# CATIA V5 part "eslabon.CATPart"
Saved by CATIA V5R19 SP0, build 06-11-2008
Part number: eslabon
Material "Dull Blue": density 7860 kg/m3, Young's modulus 2e+11 Pa, Poisson ratio 0.266
Material "Dull Blue": density 7860 kg/m3, Young's modulus 2e+11 Pa, Poisson ratio 0.266
Bounding box of the stored display mesh (mm): x 189.734 to 215.134, y -369.65 to 369.65, z 11038.485 to 11955.485
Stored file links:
  E:\Luis\Dropbox\3DIT\Parking\planos\cat 3 dit park8\Cadena\eslabon.CATPart
  E:\Luis\Dropbox\3DIT\Parking\planos\cat 3 dit park8\Cadena\Eslabon de Cadena.........................................CATProduct
  E:\Luis\Dropbox\3DIT\Parking\planos\cat 3 dit park8\Cadena\ensamble unico eslabon.CATProduct
  E:\Luis\Dropbox\3DIT\Parking\planos\cat 3 dit park8\Cadena\Soportecuna.CATProduct
  E:\Luis\Dropbox\3DIT\Parking\planos\cat 3 dit park8\ensamble Parking3d.CATProduct
  C:\Program Files (x86)\Dassault Systemes\B19\intel_a\startup\materials\Catalog.CATMaterial
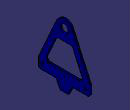
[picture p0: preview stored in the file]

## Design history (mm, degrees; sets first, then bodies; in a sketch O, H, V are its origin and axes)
External parameters (linked from other documents)
  External.P = 625
  External.b1 = 63.5
  External.b2 = 50.8
  External.d2 = 38.1
  External.g = 50.8
  External.LE = 600
Body1 (main body), material "Dull Blue"
  DatumSurface1
  DatumCurve1
  Sketch1, origin (410.9081, 7.5, 9247.3264), H (0, 1, 0), V (0, 0, 1), geometry linked from another document
  Sketch2, origin (410.9081, -1812.5, 6922.3264), H (0, 1, 0), V (0, 0, 1), geometry linked from another document
  Sketch3, origin (313.2342, -1812.5, 4597.3264), H (0, 1, 0), V (0, 0, 1), geometry linked from another document
  Sketch4 on DatumSurface4, origin (202.4342, 0, 0), H (0, 1, 0), V (0, 0, 1)
    point P2 (-312.5, 11235.4854)
    construction line L1 (0, 11835.4854) -> (0, 11235.4854)
    point P3 (0, 11235.4854)
    construction line L2 (0, 11835.4854) -> (-312.5, 11235.4854)
    line L3 (-109.3401, 11884.9296) -> (-369.65, 11309.2854)
    point P4 (-369.65, 11309.2854)
    circle A1 centre (0, 11835.4854) radius 60
    point P5 (0, 11869.2854)
    circle A2 centre (-312.5, 11235.4854) radius 19.05
    point P6 (-303.7001, 11252.3811)
    point P7 (487.5, 10734.2854)
    line L4 (-369.65, 11309.2854) -> (-369.65, 11176.963)
    point P8 (-369.65, 11072.4854)
    point P9 (-369.65, 11159.2854)
    circle A3 centre (0, 11235.4854) radius 9.525
    line L5 (-114.1377, 11159.2854) -> (-351.9723, 11159.2854)
    point P10 (-114.1377, 11159.2854)
    line L6 (-114.1377, 11159.2854) -> (-60, 11038.4854)
    point P11 (-60, 11038.4854)
    line L7 (-60, 11038.4854) -> (0, 11038.4854)
    point P12 (0, 11038.4854)
    line L8 (-369.65, 11176.963) -> (-351.9723, 11159.2854)
    point P13 (-369.65, 11176.963)
    point P14 (-351.9723, 11159.2854)
    construction line L9 (0, 11551.55) -> (0, 11955.4854)
    point P15 (0, 11551.55)
    arc A4 centre (0, 11835.4854) radius 120 from (0, 11955.4854) to (-109.3401, 11884.9296) ccw
    point P16 (0, 11835.4854)
    point P17 (0, 11955.4854)
    point P18 (0, 11955.4854)
    point P19 (-109.3401, 11884.9296)
    point P20 (109.3401, 11884.9296)
    point P21 (0, 11955.4854)
    arc A5 centre (0, 11835.4854) radius 120 from (0, 11955.4854) to (109.3401, 11884.9296) cw
    point P23 (369.65, 11309.2854)
    line L10 (109.3401, 11884.9296) -> (369.65, 11309.2854)
    point P24 (369.65, 11176.963)
    line L11 (369.65, 11309.2854) -> (369.65, 11176.963)
    point P25 (351.9723, 11159.2854)
    point P26 (114.1377, 11159.2854)
    line L12 (114.1377, 11159.2854) -> (351.9723, 11159.2854)
    point P27 (60, 11038.4854)
    line L13 (114.1377, 11159.2854) -> (60, 11038.4854)
    point P28 (0, 11038.4854)
    line L14 (60, 11038.4854) -> (0, 11038.4854)
    circle A6 centre (312.5, 11235.4854) radius 19.05
    line L15 (369.65, 11176.963) -> (351.9723, 11159.2854)
    radius A1 = 60
    radius A2 = 19.05 {= External.d2 /1000/2}
    length L1 = 600 {= External.LE /1000}
    distance P2 L4 = 57.15 {= External.d2 *1.5/1000}
    length L7 = 60
    distance P4 P9 = 150
    distance P10 P9 = 255.5123 (reference)
    angle L4 L8 = 45
    length L8 = 25
    angle L6 L5 = -294.14
    distance L1 P12 = 0
    radius A4 = 120
    distance L14 H = 11038.4854
    distance P11 V = 60 (reference)
    distance L5 P12 = 120.8
    distance P2 L5 = 76.2 {= External.g  *1.5/1000}
    distance L12 P3 = 76.2 {= External.g *1.5/1000}
    radius A3 = 9.525
    distance P2 L1 = 312.5 {= External.P /2/1000}
    vertical: L1 V, L4 V, L9 V
    coincidence: A2 P6, P6 L2, L4 P8, P12 V, L4 P9, L5 P9, P15 L1, L9 L1, P16 L2, P16 L1, L9 P17, P18 A4
    horizontal: L5 H
    tangency: A4 L3
    symmetry: P19 P20 L1, P17 P21 L1, A4 A5 L1, P4 P23 L1, L3 L10 L1, P13 P24 L1, L4 L11 L1, P14 P25 L1, P10 P26 L1, L5 L12 L1, P11 P27 L1, L6 L13 L1, P12 P28 L1, L7 L14 L1, A2 A6 L1, L8 L15 L1
  Pad1: profile Sketch4, direction (1, 0, 0), length 12.7, mirrored extent
  Sketch5, origin (253.2342, 7.5, 9247.3264), H (0, 1, 0), V (0, 0, 1), geometry linked from another document
  Sketch6, origin (253.2342, 7.5, 9247.3264), H (0, 1, 0), V (0, 0, 1), geometry linked from another document
  Sketch7 on start face of Pad1, origin (189.7342, 0, 0), H (0, -1, 0), V (0, 0, 1)
    line L1 (-87.7574, 11674.2854) -> (87.7574, 11674.2854)
    line L2 (128.76, 11647.827) -> (259.8998, 11357.827)
    line L3 (218.8972, 11294.2854) -> (-218.8972, 11294.2854)
    line L4 (-259.8998, 11357.827) -> (-128.76, 11647.827)
    arc A1 centre (87.7574, 11629.2854) radius 45 from (128.76, 11647.827) to (87.7574, 11674.2854) ccw
    arc A2 centre (-87.7574, 11629.2854) radius 45 from (-128.76, 11647.827) to (-87.7574, 11674.2854) cw
    arc A3 centre (-218.8972, 11339.2854) radius 45 from (-259.8998, 11357.827) to (-218.8972, 11294.2854) ccw
    arc A4 centre (218.8972, 11339.2854) radius 45 from (218.8972, 11294.2854) to (259.8998, 11357.827) ccw
    construction line L5 (-353.1679, 11345.7335) -> (-82.3897, 11944.5274)
    construction line L6 (-353.1679, 11345.7335) -> (-82.3897, 11944.5274)
    construction line L7 (-273.1, 11161.8476) -> (-273.1, 11259.2854)
    construction line L8 (0, 11038.4854) -> (-60, 11038.4854)
    construction arc A5 centre (0, 11809.2854) radius 120 from (111.9424, 11852.5162) to (-111.9424, 11852.5162) ccw
    point P13 (0, 11209.2854)
    reference projected line E1 (110.8472, 11881.5969) -> (359.7945, 11331.0796) from edge [start face of Pad1 | face of Pad1 from Sketch4.L3]
    reference projected line E2 (282.3223, 11159.2854) -> (114.1377, 11159.2854) from edge [start face of Pad1 | face of Pad1 from Sketch4.L5]
    reference projected line E3 (-366.9703, 11315.2112) -> (-107.04, 11890.016) from edge [start face of Pad1 | face of Pad1 from Sketch4.L10]
    reference projected circle E4 centre (0, 11835.4854) radius 60 from edge [face of Pad1 from Sketch4.A1 | start face of Pad1]
    construction line L9 (0, 11835.4854) -> (0, 10725.82)
    point P14 (0, 11835.4854)
    distance L3 L1 = 380
    radius A1 = 45
    radius A2 = 45
    radius A3 = 45
    radius A4 = 45
    distance L8 A5 = 890.8 (reference)
    distance L2 E1 = 80
    distance L3 E2 = 135
    distance L4 L6 = 80
    horizontal: L1 H
    tangency: A1 L2, A1 L1, A2 L4, A2 L1, A3 L4, A3 L3, A4 L3, A4 L2
    coincidence: L6 L5, L6 E3
    concentricity: P14 E4
    vertical: L9 V
  Pocket1: profile Sketch7, direction (1, 0, 0), length 38.1
  Plane1: type Offset, Offset 12.7, RefPlane end face of Pad1, reversed
  Sketch8 on Plane1, origin (227.8342, 0, 0), H (0, -1, 0), V (0, 0, 1)
    reference projected circle E1 centre (312.5, 11235.4854) radius 19.05 from edge [face of Pad1 from Sketch4.A2 | start face of Pad1]
    point P1 (312.5, 11235.4854)
    point P2 (-529.21, 11479.88)
    reference projected circle E2 centre (-312.5, 11235.4854) radius 19.05 from edge [face of Pad1 from Sketch4.A6 | start face of Pad1]
    point P3 (-312.5, 11235.4854)
    concentricity: P1 E1, P3 E2
  Point1: stored without definition
  Sketch9, origin (253.2342, 7.5, 9247.3264), H (0, 1, 0), V (0, 0, 1), geometry linked from another document
  DatumCurve2
  DatumSurface2 to DatumSurface4
  Sketch10 on end face of Pad1, origin (215.1342, 0, 0), H (0, 1, 0), V (0, 0, 1)
    reference projected circle E1 centre (0, 11835.4854) radius 60 from edge [end face of Pad1 | face of Pad1 from Sketch4.A1]
    point P1 (0, 11835.4854)
    concentricity: P1 E1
